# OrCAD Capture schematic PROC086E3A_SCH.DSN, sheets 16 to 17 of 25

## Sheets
16 18. FPD LINK-III SERIALIZER: size C; title: FPD LINK-III SERIALIZER
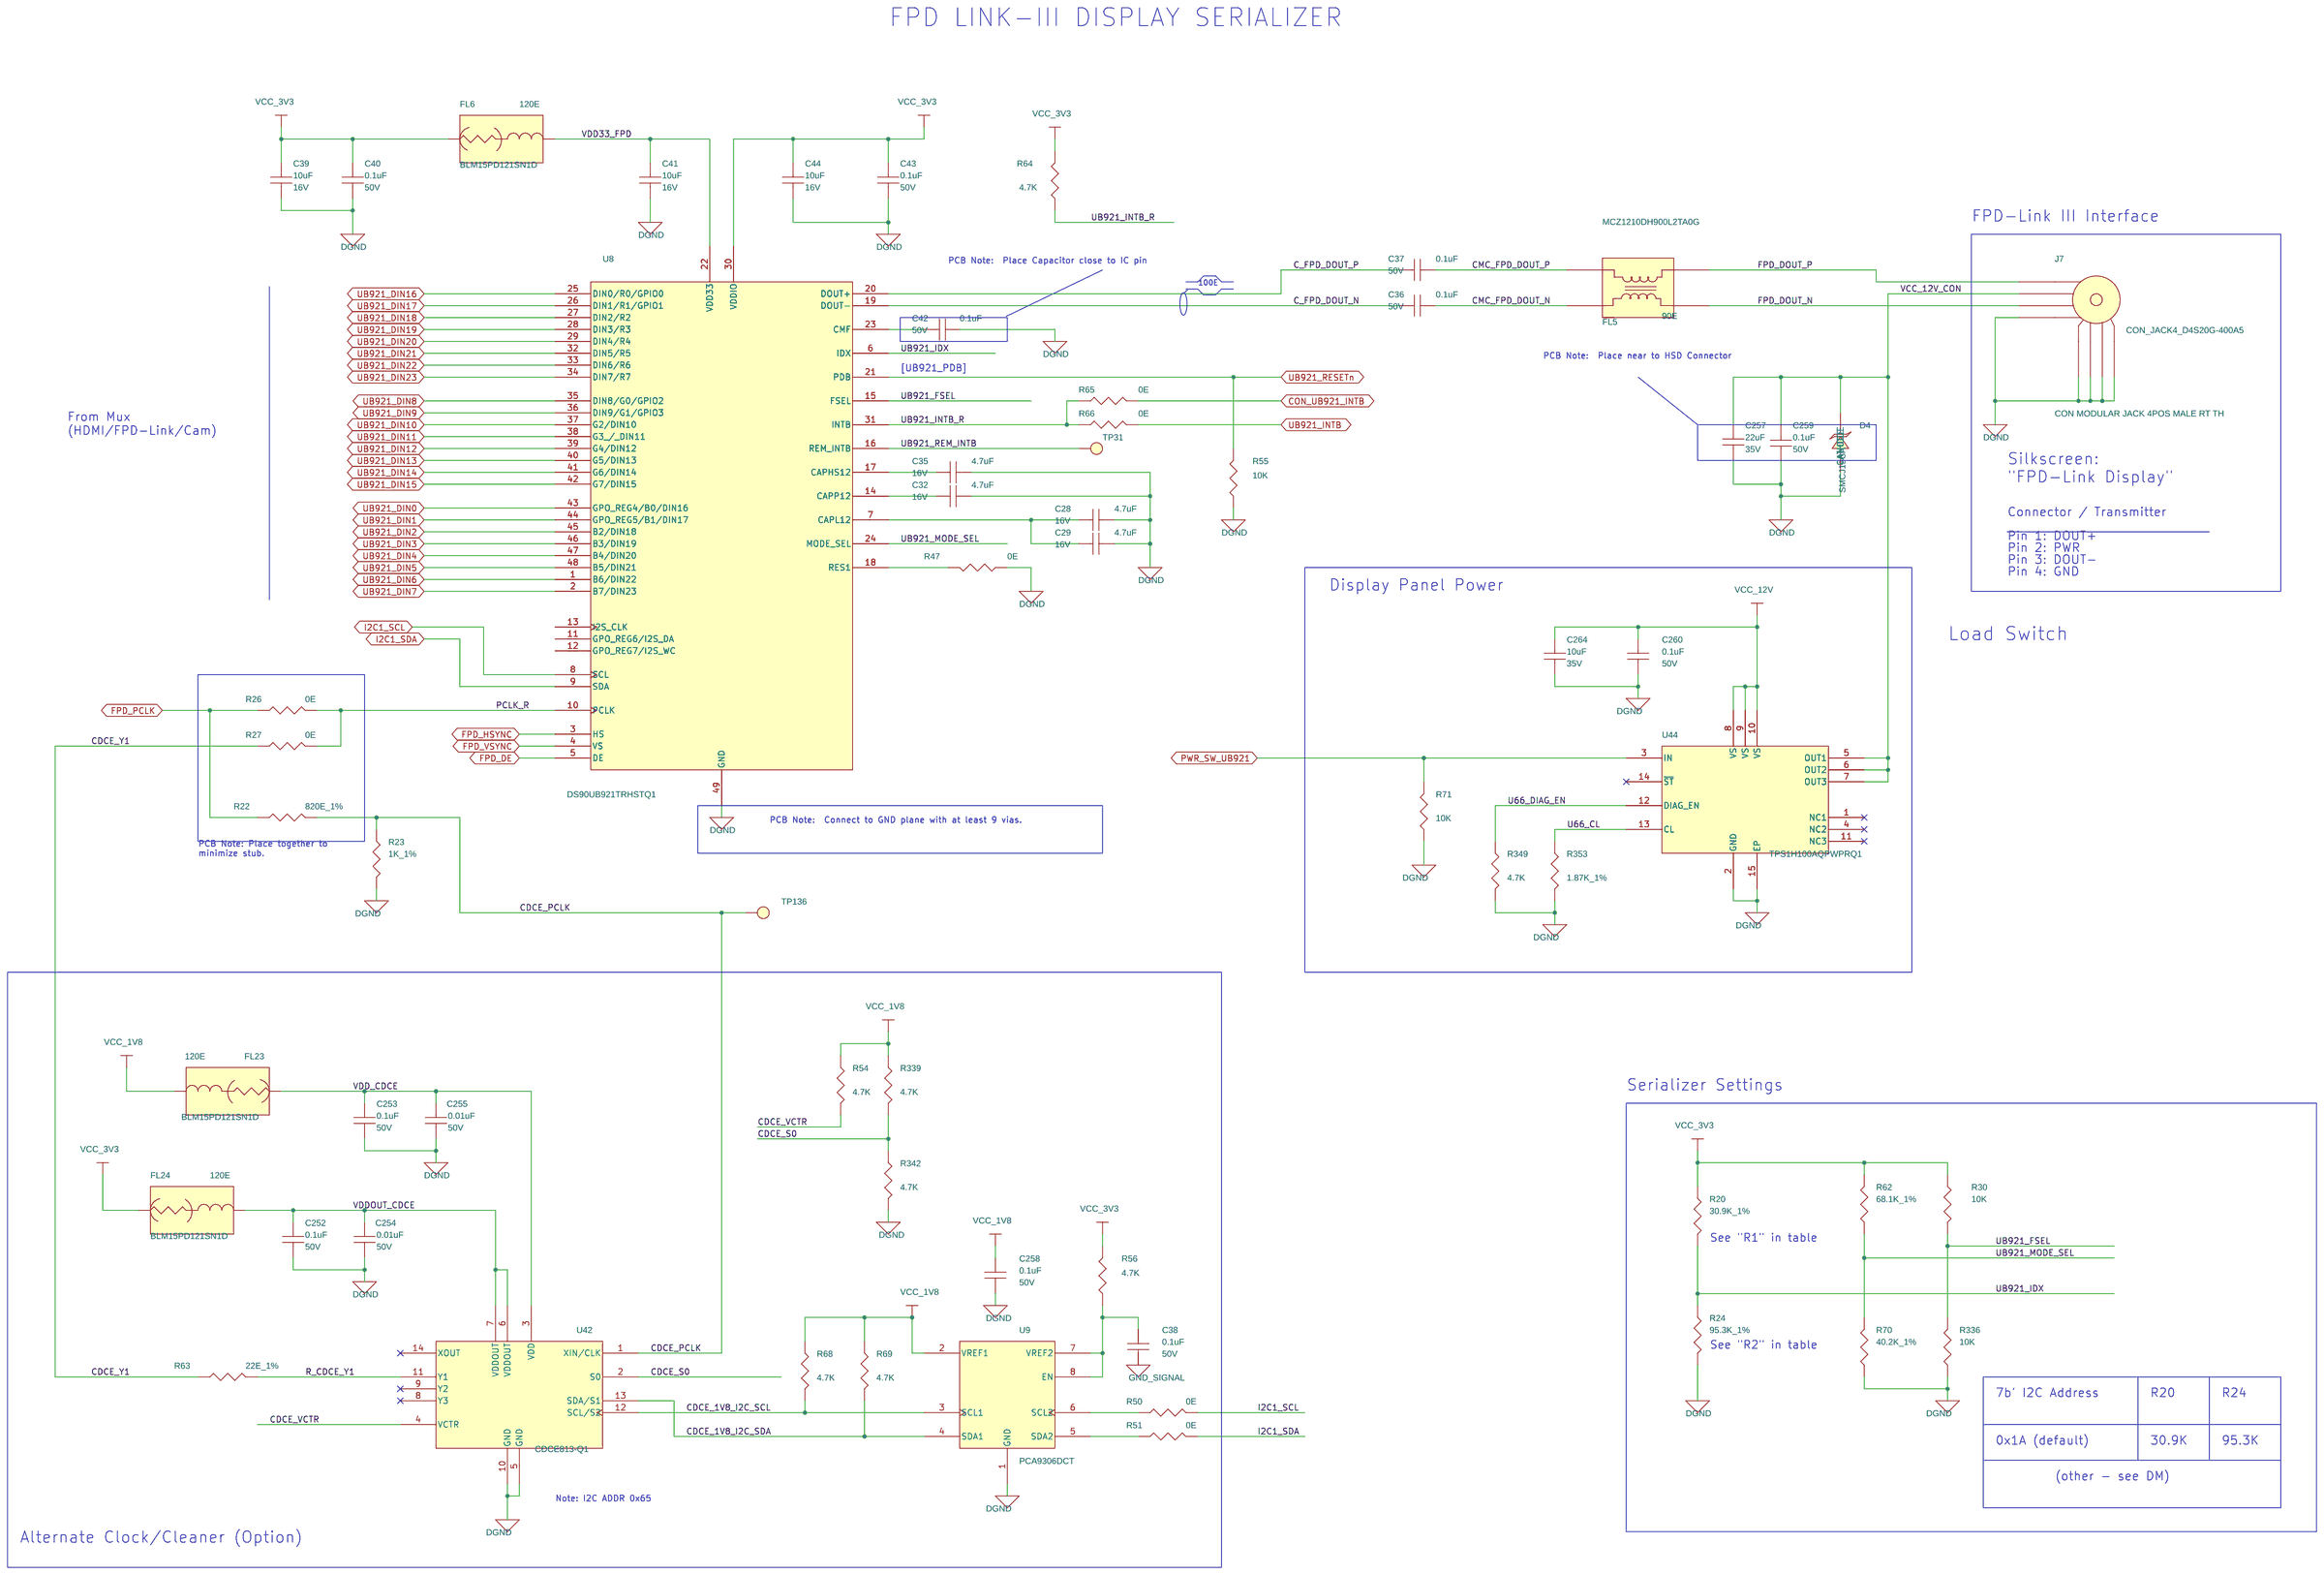
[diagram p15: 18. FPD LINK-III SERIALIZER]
17 20. LI & OV CAMERA INTERFACE: size C; title: OV CAMERA INTERFACE
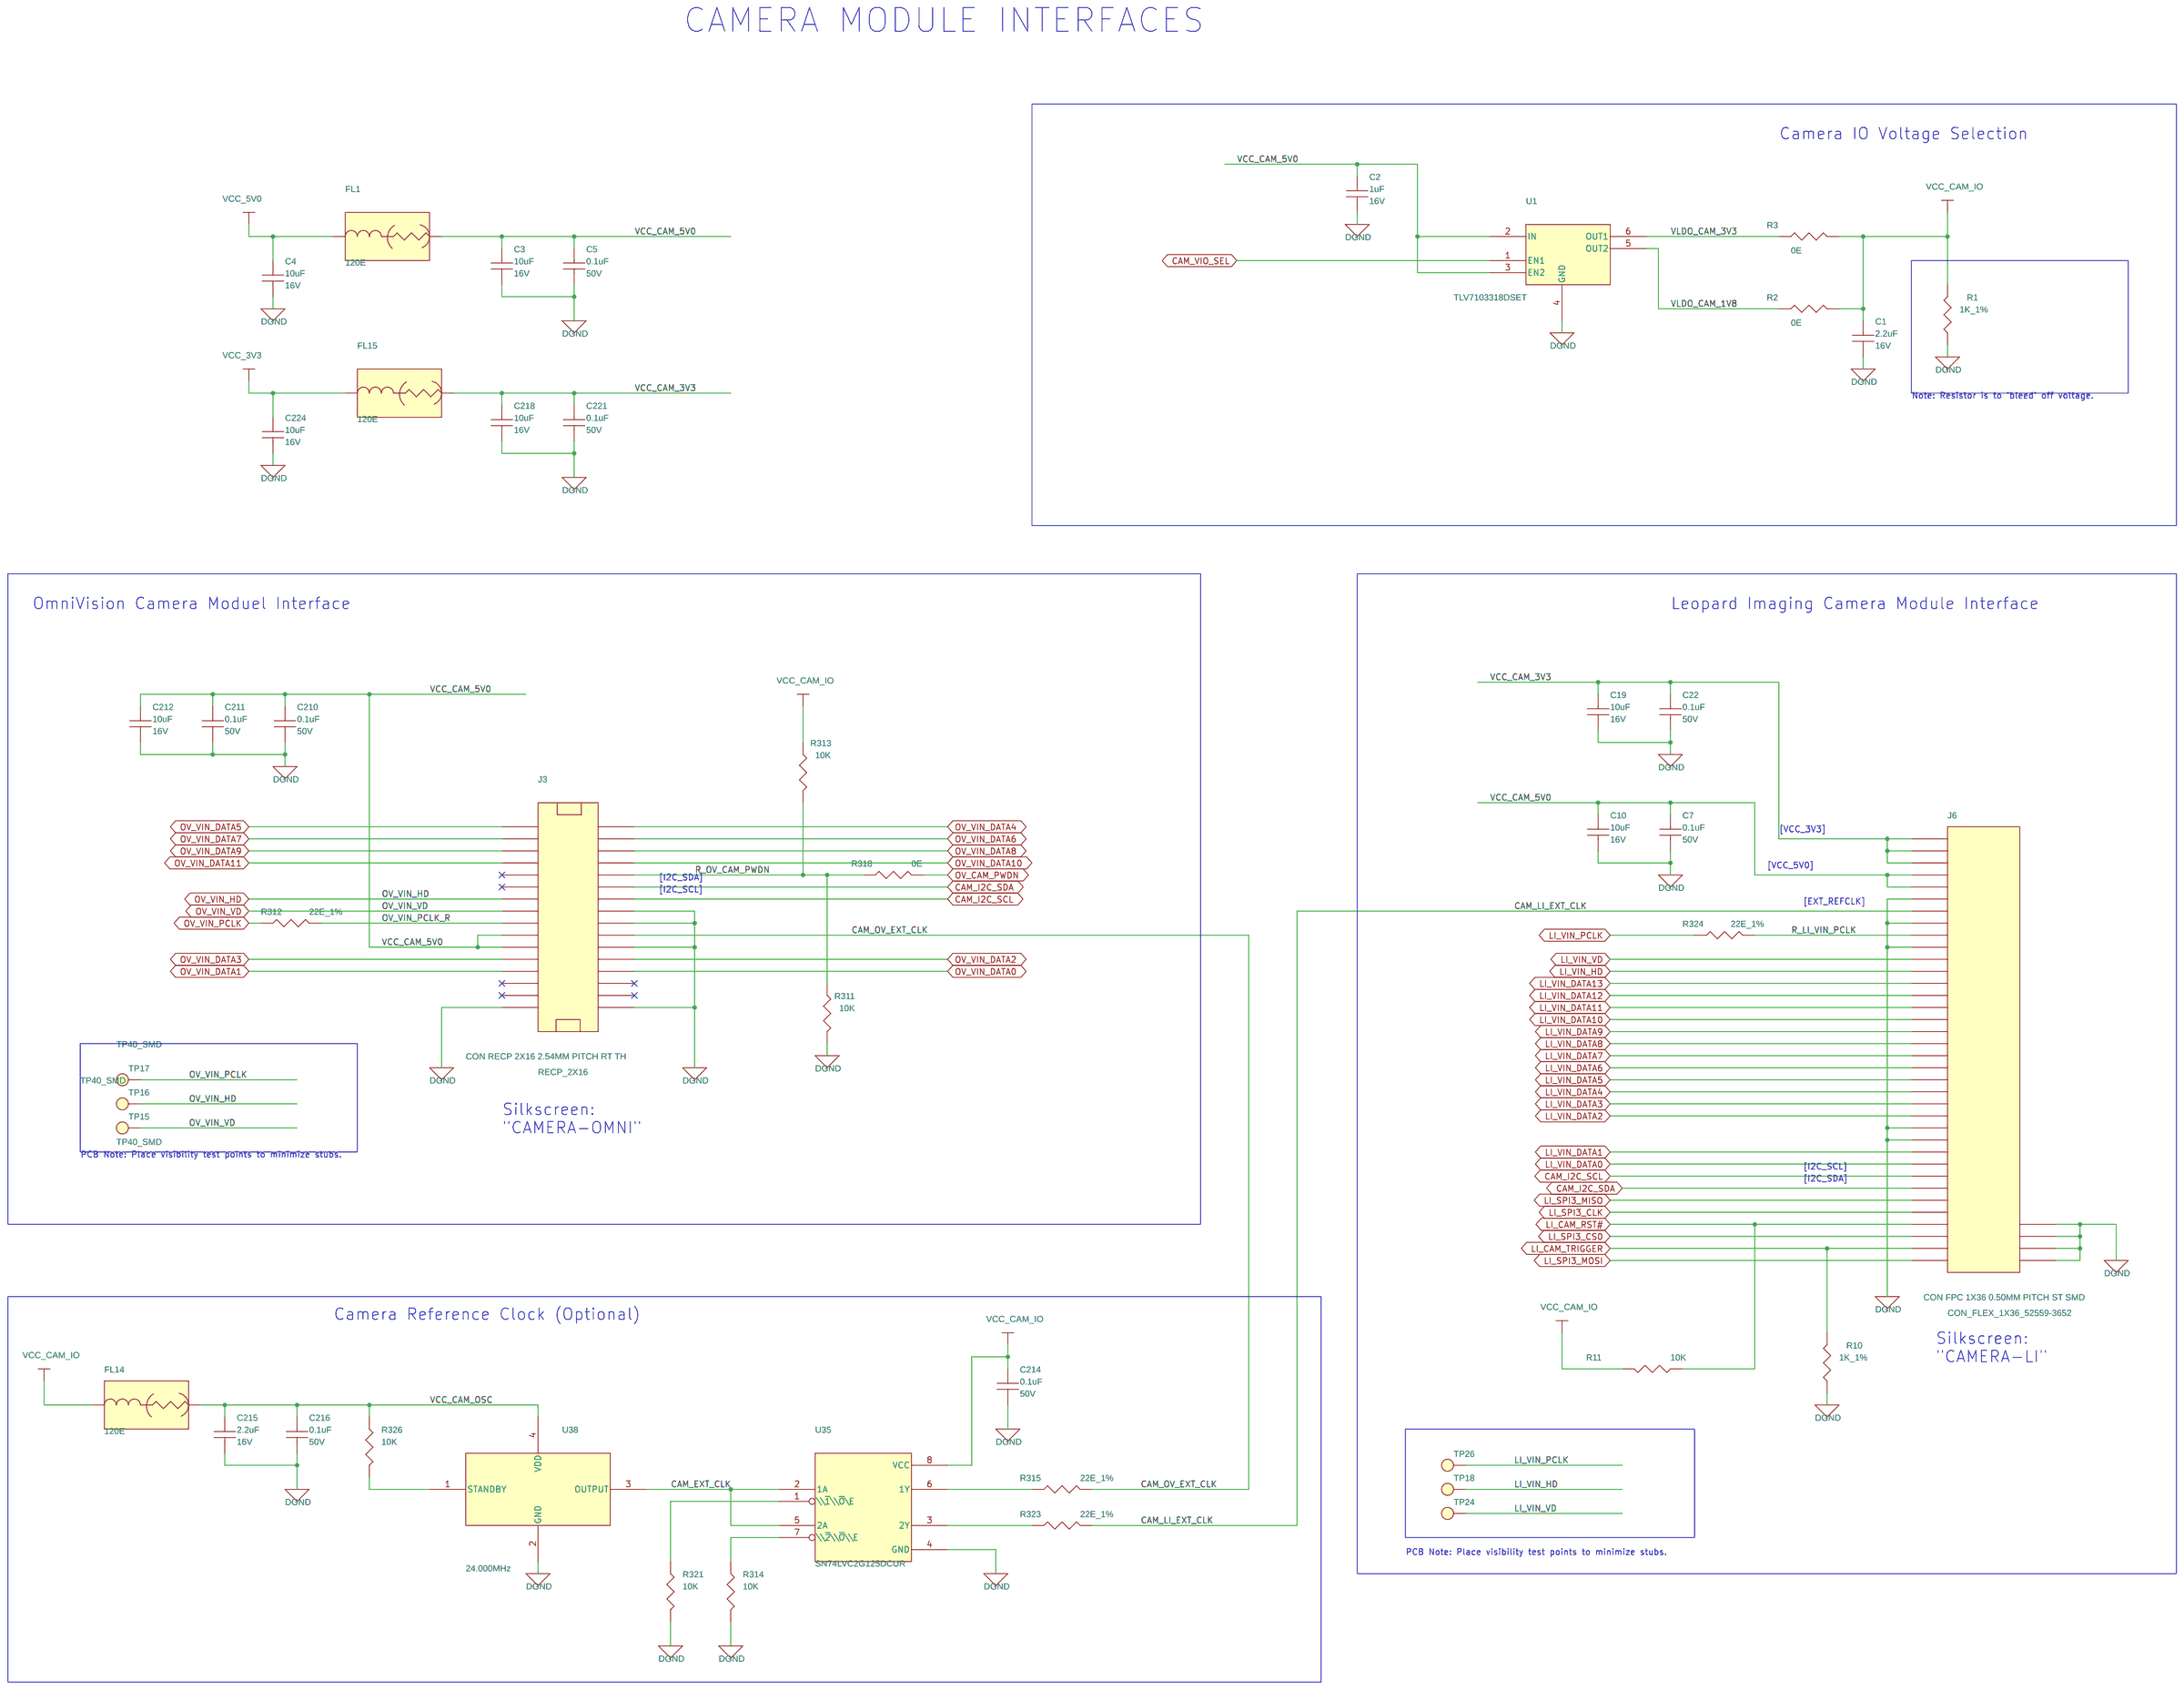
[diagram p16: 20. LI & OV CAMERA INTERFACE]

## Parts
sheet 18. FPD LINK-III SERIALIZER
C28  4.7uF  [CAP0603_1]
C29  4.7uF  [CAP0603_1]
C32  4.7uF  [CAP0603_1]
C35  4.7uF  [CAP0603_1]
C36  0.1uF  [CAP0402_0-75]
C37  0.1uF  [CAP0402_0-75]
C38  0.1uF  [CAP0402_0-75]
C39  10uF  [CAP0603_1]
C40  0.1uF  [CAP0402_0-75]
C41  10uF  [CAP0603_1]
C42  0.1uF  [CAP0402_0-75]
C43  0.1uF  [CAP0402_0-75]
C44  10uF  [CAP0603_1]
C252  0.1uF  [CAP0402_0-75]
C253  0.1uF  [CAP0402_0-75]
C254  0.01uF  [CAP0402_0-75]
C255  0.01uF  [CAP0402_0-75]
C257  22uF  [CAP1206_2]
C258  0.1uF  [CAP0402_0-75]
C259  0.1uF  [CAP0402_0-75]
C260  0.1uF  [CAP0402_0-75]
C264  10uF  [CAP1206_2]
D4  SMCJ15CA  [DIO_SMC]
FL5  90E  [FILT4_MCZ1210DH_60X50_SMD_0-6]
FL6  120E  [EMIFIL_BLM15A_0402_0-6]
FL23  120E  [EMIFIL_BLM15A_0402_0-6]
FL24  120E  [EMIFIL_BLM15A_0402_0-6]
J7  CON_JACK4_D4S20G-400A5  [CON_JACK4_D4S20G-400A5_P_R_T_10-6]
R20  30.9K_1%  [RES0402_0-5]
R22  820E_1%  [RES0402_0-5]
R23  1K_1%  [RES0402_0-5]
R24  95.3K_1%  [RES0402_0-5]
R26  0E  [RES0402_0-5]
R27  0E  [RES0402_0-5]
R30  10K  [RES0402_0-5]
R47  0E  [RES0402_0-5]
R50  0E  [RES0402_0-5]
R51  0E  [RES0402_0-5]
R54  4.7K  [RES0402_0-5]
R55  10K  [RES0402_0-5]
R56  4.7K  [RES0402_0-5]
R62  68.1K_1%  [RES0402_0-5]
R63  22E_1%  [RES0402_0-5]
R64  4.7K  [RES0402_0-5]
R65  0E  [RES0402_0-5]
R66  0E  [RES0402_0-5]
R68  4.7K  [RES0402_0-5]
R69  4.7K  [RES0402_0-5]
R70  40.2K_1%  [RES0402_0-5]
R71  10K  [RES0402_0-5]
R336  10K  [RES0402_0-5]
R339  4.7K  [RES0402_0-5]
R342  4.7K  [RES0402_0-5]
R349  4.7K  [RES0402_0-5]
R353  1.87K_1%  [RES0402_0-5]
TP31  TP40_SMD  [TP40_SMD]
TP136  TP20_SMD  [TP20_SMD]
U8  DS90UB921TRHSTQ1  [QFN48_19-68_280X280_0-8_EP5-2]
U9  PCA9306DCT  [SSOP8_25-59_120X110]
U42  CDCE813-Q1  [TSSOP14_25-59_205X180_1-2]
U44  TPS1H100AQPWPRQ1  [HTSSOP14_TPS1H100-Q1_180X200_1-2]
sheet 20. LI & OV CAMERA INTERFACE
C1  2.2uF  [CAP0805_1-5]
C2  1uF  [CAP0402_0-5]
C3  10uF  [CAP0603_1]
C4  10uF  [CAP0603_1]
C5  0.1uF  [CAP0402_0-75]
C7  0.1uF  [CAP0402_0-75]
C10  10uF  [CAP0603_1]
C19  10uF  [CAP0603_1]
C22  0.1uF  [CAP0402_0-75]
C210  0.1uF  [CAP0402_0-75]
C211  0.1uF  [CAP0402_0-75]
C212  10uF  [CAP0603_1]
C214  0.1uF  [CAP0402_0-75]
C215  2.2uF  [CAP0805_1-5]
C216  0.1uF  [CAP0402_0-75]
C218  10uF  [CAP0603_1]
C221  0.1uF  [CAP0402_0-75]
C224  10uF  [CAP0603_1]
FL1  120E  [EMIFIL_BLM15A_0402_0-6]
FL14  120E  [EMIFIL_BLM15A_0402_0-6]
FL15  120E  [EMIFIL_BLM15A_0402_0-6]
J3  RECP_2X16  [RECPT_2X16_SSW-116-D-RA_R_T_5]
J6  CON_FLEX_1X36_52559-3652  [CON_FLEX1X36_52559-36_S_S_S_5-3]
R1  1K_1%  [RES0402_0-5]
R2  0E  [RES0402_0-5]
R3  0E  [RES0402_0-5]
R10  1K_1%  [RES0402_0-5]
R11  10K  [RES0402_0-5]
R311  10K  [RES0402_0-5]
R312  22E_1%  [RES0402_0-5]
R313  10K  [RES0402_0-5]
R314  10K  [RES0402_0-5]
R315  22E_1%  [RES0402_0-5]
R318  0E  [RES0402_0-5]
R321  10K  [RES0402_0-5]
R323  22E_1%  [RES0402_0-5]
R324  22E_1%  [RES0402_0-5]
R326  10K  [RES0402_0-5]
TP15  TP40_SMD  [TP40_SMD]
TP16  TP40_SMD  [TP40_SMD]
TP17  TP40_SMD  [TP40_SMD]
TP18  TP40_SMD  [TP40_SMD]
TP24  TP40_SMD  [TP40_SMD]
TP26  TP40_SMD  [TP40_SMD]
U1  TLV7103318DSET  [WSON6_19-68_60X60]
U35  SN74LVC2G125DCUR  [VSSOP8_19-68_85X95]
U38  24.000MHz  [OSC4_ASDMB_100X85_SMD_0-9]

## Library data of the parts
C28 C29 C32 C35 = CAP: CAP CERAMIC 4.7uF 16V 10% X6S 0603; Chkd/date: MANIRAJA/050618; Crtd /date: ALVY/050618; Custom_Duty: 15%; Customs_HS_Code: 85322990; Distributor_name: DIGIKEY; Distributor_part_number: 445-9118-1-ND; Footprint Path: Y:\MIS_DATABASE\Library\ALTIUM_TOOL\PCB_FOOTPRINTS\Altium_Footprint_Lib.PcbLib; Height: 1.00MM; Library Path: Y:\MIS_DATABASE\Library\ALTIUM_TOOL\SCHEMATICS_PARTS\MS_DISCRETE_Library.schlib; Mfr_name: TDK CORPORATION; Mfr_part_number: C1608X6S1C475K080AC; Mistral Part No: 120018060012-R; Package: 0603; Part_type: CAPACITORS\CERAMIC; Project: NPOL_RDAQ_ONBOARD-RX; RoHS: RoHS; Temperature: -55°C+105°C; Tolerance: 10%; Voltage: 16V; Wattage: NA; Weight: 2mg; Datasheet: Y:\MIS_DATABASE\DATASHEETS\CAPACITORS\TDK_C-SER-JUL17.PDF
C5 C7 C22 C36-C38 C40 C42 C43 C210 C211 C214 C216 C221 C252 C253 C258-C260 = CAP: CAP CERAMIC 0.1uF 50V 10% X7R 0402; Chkd/date: VASANTHA/281216; Crtd /date: CHAITHANYA/051011; Custom_Duty: 15%; Customs_HS_Code: 85322990; Distributor_name: DIGIKEY; Distributor_part_number: 445-173610-1-ND; Footprint Path: Y:\MIS_DATABASE\Library\ALTIUM_TOOL\PCB_FOOTPRINTS\Altium_Footprint_Lib.PcbLib; Height: 0.60MM; Library Path: Y:\MIS_DATABASE\Library\ALTIUM_TOOL\SCHEMATICS_PARTS\MS_DISCRETE_Library.schlib; Mfr_name: TDK CORPORATION; Mfr_part_number: C1005X7R1H104K050BE; Mistral Part No: 120011100014-R; Package: 0402; Part_type: CAPACITORS\CERAMIC; Project: VP-4000-BASE-BOARD; RoHS: RoHS; Temperature: -55°C+125°C; Tolerance: 10%; Voltage: 50V; Wattage: NA; Weight: 0.65mg; Datasheet: Y:\MIS_DATABASE\DATASHEETS\CAPACITORS\TDK_C-SER_FEB19.PDF
C3 C4 C10 C19 C39 C41 C44 C212 C218 C224 = CAP: CAP CERAMIC 10uF 16V 20% X6S 0603; Chkd/date: VASANTHA/170117; Crtd /date: VASANTHA/170117; Custom_Duty: 15%; Customs_HS_Code: 85322990; Distributor_name: DIGIKEY; Distributor_part_number: 490-7198-1-ND; Footprint Path: Y:\MIS_DATABASE\Library\ALTIUM_TOOL\PCB_FOOTPRINTS\Altium_Footprint_Lib.PcbLib; Height: 0.90MM; Library Path: Y:\MIS_DATABASE\Library\ALTIUM_TOOL\SCHEMATICS_PARTS\MS_DISCRETE_Library.schlib; Mfr_name: MURATA; Mfr_part_number: GRM188C81C106MA73D; Mistral Part No: 120017010004-R; Package: 0603; Part_type: CAPACITORS\CERAMIC; Project: TRMM_SMART-M_PS; RoHS: RoHS; Temperature: -55°C+105°C; Tolerance: 20%; Voltage: 16V; Wattage: NA; Weight: 6.3mg; Datasheet: Y:\MIS_DATABASE\DATASHEETS\CAPACITORS\MURATA-GXX-SER_NOV17.PDF
C254 C255 = CAP: CAP CERAMIC 0.01uF 50V 10% X7R 0402; Chkd/date: SHREESHAIL/301105; Crtd /date: MAZHAR/040505; Custom_Duty: 15%; Customs_HS_Code: 85322990; Distributor_name: DIGIKEY; Distributor_part_number: 399-3066-1-ND; Footprint Path: Y:\MIS_DATABASE\Library\ALTIUM_TOOL\PCB_FOOTPRINTS\Altium_Footprint_Lib.PcbLib; Height: 0.55MM; Library Path: Y:\MIS_DATABASE\Library\ALTIUM_TOOL\SCHEMATICS_PARTS\MS_DISCRETE_Library.schlib; Mfr_name: KEMET; Mfr_part_number: C0402C103K5RACTU; Mistral Part No: 120009030025-R; Package: 0402; Part_type: CAPACITORS\CERAMIC; Project: G4_SVGA; RoHS: RoHS; Temperature: -55°C+125°C; Tolerance: 10%; Voltage: 50V; Wattage: NA; Weight: 0.65mg; Datasheet: Y:\MIS_DATABASE\DATASHEETS\CAPACITORS\KEMET-C-X7R.PDF
C257 = CAP: CAP CERAMIC 22uF 35V 20% X5R 1206; Chkd/date: MANIRAJA/130318; Crtd /date: MANIRAJA/130318; Custom_Duty: 15%; Customs_HS_Code: 85322990; Distributor_name: DIGIKEY; Distributor_part_number: 445-8045-1-ND; Footprint Path: Y:\MIS_DATABASE\Library\ALTIUM_TOOL\PCB_FOOTPRINTS\Altium_Footprint_Lib.PcbLib; Height: 1.80MM; Library Path: Y:\MIS_DATABASE\Library\ALTIUM_TOOL\SCHEMATICS_PARTS\MS_DISCRETE_Library.schlib; Mfr_name: TDK CORPORATION; Mfr_part_number: C3216X5R1V226M160AC; Mistral Part No: 120018030003-R; Package: 1206; Part_type: CAPACITORS\CERAMIC; Project: TI_SVB_MAXWELL_VPS; RoHS: RoHS; Temperature: -55°C+85°C; Tolerance: 20%; Voltage: 35V; Wattage: NA; Weight: 16.2mg; Datasheet: Y:\MIS_DATABASE\DATASHEETS\CAPACITORS\C3216X5R1V226M160AC.PDF
C264 = CAP: CAP CERAMIC 10uF 35V 10% X5R 1206; Chkd/date: MANIRAJA/160519; Crtd /date: ALVY/160519; Custom_Duty: 15%; Customs_HS_Code: 85322990; Distributor_name: DIGIKEY; Distributor_part_number: 587-2484-1-ND; Footprint Path: Y:\MIS_DATABASE\Library\ALTIUM_TOOL\PCB_FOOTPRINTS\Altium_Footprint_Lib.PcbLib; Height: 1.80MM; Library Path: Y:\MIS_DATABASE\Library\ALTIUM_TOOL\SCHEMATICS_PARTS\MS_DISCRETE_Library.schlib; Mfr_name: TAIYO YUDEN; Mfr_part_number: GMK316BJ106KL-T; Mistral Part No: 120019050012-R; Package: 1206; Part_type: CAPACITORS\CERAMIC; Project: J7ES_SOM_DUAL-LEO_PMIC; RoHS: RoHS; Temperature: -55°C+85°C; Tolerance: 10%; Voltage: 35V; Wattage: NA; Weight: 16.2mg; Datasheet: Y:\MIS_DATABASE\DATASHEETS\CAPACITORS\TY-EMKXXX-2019.PDF
D4 = DIODE_TVS: DIODE TVS 1500W 15V SMC; Chkd/date: SUHAS/061010; Crtd /date: MAZHAR/011007; Custom_Duty: 15%; Customs_HS_Code: 85412900; Distributor_name: DIGIKEY; Distributor_part_number: SMCJ15CALFCT-ND; Height: 2.62MM; Mfr_name: LITTLE FUSE; Mistral Part No: 130009030286-R; Package: SMC; Part_type: DIODE\TVS; Project: TELEMETRY ENCODER; RoHS: RoHS; Temperature: -55°C+150°C; Voltage: 15V; Wattage: 1500W; Weight: 0.21g; Datasheet: Y:\MIS_DATABASE\DATASHEETS\DISCRETES\DIODES\SMCJ-LITT.PDF
FL5 = EMIFILTER_ACM: FILTER COMMON MODE 90E 100mA SMD; Chkd/date: MANIRAJA/220818; Crtd /date: ALVY/220818; Custom_Duty: 24%; Customs_HS_Code: 85437099; Distributor_name: DIGIKEY; Distributor_part_number: 445-174550-1-ND; Footprint Path: Y:\MIS_DATABASE\Library\ALTIUM_TOOL\PCB_FOOTPRINTS\Altium_Footprint_Lib.PcbLib; Height: 0.60MM; Library Path: Y:\MIS_DATABASE\Library\ALTIUM_TOOL\SCHEMATICS_PARTS\MS_FILTER_Library.schlib; Mfr_name: TDK CORPORATION; Mfr_part_number: MCZ1210DH900L2TA0G; Mistral Part No: 130018080027-R; Package: SMD; Part_type: FILTER; Project: TI_J7ES_EVM_FUSION2_SER_CAP; RoHS: RoHS; Temperature: -40°C+85°C; Tolerance: 25%; Voltage: NA; Wattage: NA; Weight: 3mg; Datasheet: Y:\MIS_DATABASE\DATASHEETS\ICS\MISC\MCZ1210DH-SER.PDF
FL1 FL6 FL14 FL15 FL23 FL24 = EMIFILTER_IND: IND FERRITE BEAD CHIP 120E 1.3A 0402; Chkd/date: VASANTHA/010117; Crtd /date: CHAITHANYA/150312; Custom_Duty: 24%; Customs_HS_Code: 85437099; Distributor_name: DIGIKEY; Distributor_part_number: 490-5203-1-ND; Footprint Path: Y:\MIS_DATABASE\Library\ALTIUM_TOOL\PCB_FOOTPRINTS\Altium_Footprint_Lib.PcbLib; Height: 0.55MM; Library Path: Y:\MIS_DATABASE\Library\ALTIUM_TOOL\SCHEMATICS_PARTS\MS_FILTER_Library.schlib; Mfr_name: MURATA; Mfr_part_number: BLM15PD121SN1D; Mistral Part No: 130012030043-R; Package: 0402; Part_type: FILTER; Project: GEN_3-8; RoHS: RoHS; Temperature: -55°C+125°C; Tolerance: 25%; Voltage: NA; Wattage: NA; Weight: 0.65mg; Datasheet: Y:\MIS_DATABASE\DATASHEETS\DISCRETES\INDUCTORS\BLM15X-SER.PDF
J7 = CON_JACK4_EXG.0B.304: CON MODULAR JACK 4POS MALE RT TH; Chkd/date: MANIRAJA/031018; Crtd /date: ALVY/070818; Custom_Duty: 24%; Customs_HS_Code: 85369090; Distributor_name: DIGIKEY; Distributor_part_number: 1868-1516-1-ND; Footprint Path: Y:\MIS_DATABASE\Library\ALTIUM_TOOL\PCB_FOOTPRINTS\Altium_Footprint_Lib.PcbLib; Height: 10.60MM; Library Path: Y:\MIS_DATABASE\Library\ALTIUM_TOOL\SCHEMATICS_PARTS\MS_CONNECTOR_Library.schlib; Mfr_name: ROSENBERGER; Mfr_part_number: D4S20G-400A5-C; Mistral Part No: 150018080004-R; Package: THRU-HOLE; Part_type: CONNECTOR\JACK; Project: TI_J7ES_EVM_IB; RoHS: RoHS; Temperature: -40°C+105°C; Tolerance: NA; Voltage: NA; Wattage: NA; Weight: 8.6g; Datasheet: Y:\MIS_DATABASE\DATASHEETS\CONNECTORS\D4S20G-400A5-Y.PDF
R20 = RESISTOR: RES 30.9K 1/10W 1% 0402; Chkd/date: MAZHAR/080311; Crtd /date: BAVISH/230211; Custom_Duty: 15%; Customs_HS_Code: 85332119; Distributor_name: DIGIKEY; Distributor_part_number: P30.9KLCT-ND; Footprint Path: Y:\MIS_DATABASE\Library\ALTIUM_TOOL\PCB_FOOTPRINTS\Altium_Footprint_Lib.PcbLib; Height: 0.40MM; Library Path: Y:\MIS_DATABASE\Library\ALTIUM_TOOL\SCHEMATICS_PARTS\MS_DISCRETE_Library.schlib; Mfr_name: PANASONIC-ECG; Mfr_part_number: ERJ-2RKF3092X; Mistral Part No: 110011020022-R; Package: 0402; Part_type: RESISTORS\FIXED; Project: GOLDEN-I; RoHS: RoHS; Temperature: -55°C+155°C; Tolerance: 1%; Voltage: NA; Wattage: 1/10W; Weight: 0.8mg; Datasheet: Y:\MIS_DATABASE\DATASHEETS\RESISTORS\PAN-ERJSER_NOV17.PDF
R22 = RESISTOR: RES 820E 1/10W 1% 0402; Assembly_Instruction: DNI; Chkd/date: MAZHAR/150709; Crtd /date: USMAN/020409; Custom_Duty: 15%; Customs_HS_Code: 85332119; Distributor_name: DIGIKEY; Distributor_part_number: P820LCT-ND; Footprint Path: Y:\MIS_DATABASE\Library\ALTIUM_TOOL\PCB_FOOTPRINTS\Altium_Footprint_Lib.PcbLib; Height: 0.40MM; Library Path: Y:\MIS_DATABASE\Library\ALTIUM_TOOL\SCHEMATICS_PARTS\MS_DISCRETE_Library.schlib; Mfr_name: PANASONIC-ECG; Mfr_part_number: ERJ-2RKF8200X; Mistral Part No: 110009031230-R; Package: 0402; Part_type: RESISTORS\FIXED; Project: AXON; RoHS: RoHS; Temperature: -55°C+155°C; Tolerance: 1%; Voltage: NA; Wattage: 1/10W; Weight: 0.8mg; Datasheet: Y:\MIS_DATABASE\DATASHEETS\RESISTORS\PAN-ERJSER_NOV17.PDF
R1 R10 R23 = RESISTOR: RES 1K 1/10W 1% 0402; Chkd/date: VASANTHA/281216; Crtd /date: MAZHAR/150506; Custom_Duty: 15%; Customs_HS_Code: 85332119; Distributor_name: DIGIKEY; Distributor_part_number: P1.00KLCT-ND; Footprint Path: Y:\MIS_DATABASE\Library\ALTIUM_TOOL\PCB_FOOTPRINTS\Altium_Footprint_Lib.PcbLib; Height: 0.40MM; Library Path: Y:\MIS_DATABASE\Library\ALTIUM_TOOL\SCHEMATICS_PARTS\MS_DISCRETE_Library.schlib; Mfr_name: PANASONIC-ECG; Mfr_part_number: ERJ-2RKF1001X; Mistral Part No: 110009030411-R; Package: 0402; Part_type: RESISTORS\FIXED; Project: VOCERA; RoHS: RoHS; Temperature: -55°C+155°C; Tolerance: 1%; Voltage: NA; Wattage: 1/10W; Weight: 0.8mg; Datasheet: Y:\MIS_DATABASE\DATASHEETS\RESISTORS\PAN-ERJSER_NOV17.PDF
R24 = RESISTOR: RES 95.3K 1/16W 1% 0402; Chkd/date: VASANTHA/061216; Crtd /date: CHAITHANYA/060612; Custom_Duty: 15%; Customs_HS_Code: 85332119; Distributor_name: DIGIKEY; Distributor_part_number: 541-95.3KLCT-ND; Footprint Path: Y:\MIS_DATABASE\Library\ALTIUM_TOOL\PCB_FOOTPRINTS\Altium_Footprint_Lib.PcbLib; Height: 0.40MM; Library Path: Y:\MIS_DATABASE\Library\ALTIUM_TOOL\SCHEMATICS_PARTS\MS_DISCRETE_Library.schlib; Mfr_name: VISHAY; Mfr_part_number: CRCW040295K3FKED; Mistral Part No: 110012060003-R; Package: 0402; Part_type: RESISTORS\FIXED; Project: GEN_3-8_DB; RoHS: RoHS; Temperature: -55°C+155°C; Tolerance: 1%; Voltage: NA; Wattage: 1/16W; Weight: 0.65mg; Datasheet: Y:\MIS_DATABASE\DATASHEETS\RESISTORS\CRCW0603.PDF
R2 R3 R26 R47 R65 R318 = RESISTOR: RES 0E 1/10W JUMPER 0402; Chkd/date: VASANTHA/061216; Crtd /date: NAVEED/201014; Custom_Duty: 15%; Customs_HS_Code: 85332119; Distributor_name: DIGIKEY; Distributor_part_number: P0.0JCT-ND; Footprint Path: Y:\MIS_DATABASE\Library\ALTIUM_TOOL\PCB_FOOTPRINTS\Altium_Footprint_Lib.PcbLib; Height: 0.40MM; IBISSP_MODLES: VALUE REPEATING 2 TIME; Library Path: Y:\MIS_DATABASE\Library\ALTIUM_TOOL\SCHEMATICS_PARTS\MS_DISCRETE_Library.schlib; Mfr_name: PANASONIC-ECG; Mfr_part_number: ERJ-2GE0R00X; Mistral Part No: 110018030052-R; Package: 0402; Part_type: RESISTORS\FIXED; Project: AEGIS POM; RoHS: RoHS; Temperature: -55°C+155°C; Tolerance: NA; Voltage: NA; Wattage: 1/10W; Weight: 0.8mg; Datasheet: Y:\MIS_DATABASE\DATASHEETS\RESISTORS\PAN-ERJSER_NOV17.PDF
R27 R50 R51 = RESISTOR: RES 0E 1/10W JUMPER 0402; Assembly_Instruction: DNI; Chkd/date: VASANTHA/061216; Crtd /date: NAVEED/201014; Custom_Duty: 15%; Customs_HS_Code: 85332119; Distributor_name: DIGIKEY; Distributor_part_number: P0.0JCT-ND; Footprint Path: Y:\MIS_DATABASE\Library\ALTIUM_TOOL\PCB_FOOTPRINTS\Altium_Footprint_Lib.PcbLib; Height: 0.40MM; IBISSP_MODLES: VALUE REPEATING 2 TIME; Library Path: Y:\MIS_DATABASE\Library\ALTIUM_TOOL\SCHEMATICS_PARTS\MS_DISCRETE_Library.schlib; Mfr_name: PANASONIC-ECG; Mfr_part_number: ERJ-2GE0R00X; Mistral Part No: 110018030052-R; Package: 0402; Part_type: RESISTORS\FIXED; Project: AEGIS POM; RoHS: RoHS; Temperature: -55°C+155°C; Tolerance: NA; Voltage: NA; Wattage: 1/10W; Weight: 0.8mg; Datasheet: Y:\MIS_DATABASE\DATASHEETS\RESISTORS\PAN-ERJSER_NOV17.PDF
R30 R311 R313 = RESISTOR: RES 10K 1/16W 5% 0402; Assembly_Instruction: DNI; Chkd/date: VASANTHA/061216; Crtd /date: MAZHAR/230805; Custom_Duty: 15%; Customs_HS_Code: 85332119; Distributor_name: DIGIKEY; Distributor_part_number: 311-10KJRCT-ND; Footprint Path: Y:\MIS_DATABASE\Library\ALTIUM_TOOL\PCB_FOOTPRINTS\Altium_Footprint_Lib.PcbLib; Height: 0.40MM; Library Path: Y:\MIS_DATABASE\Library\ALTIUM_TOOL\SCHEMATICS_PARTS\MS_DISCRETE_Library.schlib; Mfr_name: YAGEO AMERICA; Mfr_part_number: RC0402JR-0710KL; Mistral Part No: 110011060021-R; Package: 0402; Part_type: RESISTORS\FIXED; Project: HSE; RoHS: RoHS; Temperature: -55°C+155°C; Tolerance: 5%; Voltage: NA; Wattage: 1/16W; Weight: 0.65mg; Datasheet: Y:\MIS_DATABASE\DATASHEETS\RESISTORS\RCXXXXL-SER_MAR18.PDF
R54 R56 R64 R68 R69 R339 R349 = RESISTOR: RES 4.7K 1/16W 5% 0402; Chkd/date: VASANTHA/281216; Crtd /date: BAVISH/010611; Custom_Duty: 15%; Customs_HS_Code: 85332119; Distributor_name: DIGIKEY; Distributor_part_number: 541-4.7KJCT-ND; Footprint Path: Y:\MIS_DATABASE\Library\ALTIUM_TOOL\PCB_FOOTPRINTS\Altium_Footprint_Lib.PcbLib; Height: 0.40MM; Library Path: Y:\MIS_DATABASE\Library\ALTIUM_TOOL\SCHEMATICS_PARTS\MS_DISCRETE_Library.schlib; Mfr_name: VISHAY; Mfr_part_number: CRCW04024K70JNED; Mistral Part No: 110011060001-R; Package: 0402; Part_type: RESISTORS\FIXED; Project: AM4515_EVM_LCD; RoHS: RoHS; Temperature: -55°C+155°C; Tolerance: 5%; Voltage: NA; Wattage: 1/16W; Weight: 0.65mg; Datasheet: Y:\MIS_DATABASE\DATASHEETS\RESISTORS\CRCW0603.PDF
R11 R55 R71 R314 R321 R326 R336 = RESISTOR: RES 10K 1/16W 5% 0402; Chkd/date: VASANTHA/061216; Crtd /date: MAZHAR/230805; Custom_Duty: 15%; Customs_HS_Code: 85332119; Distributor_name: DIGIKEY; Distributor_part_number: 311-10KJRCT-ND; Footprint Path: Y:\MIS_DATABASE\Library\ALTIUM_TOOL\PCB_FOOTPRINTS\Altium_Footprint_Lib.PcbLib; Height: 0.40MM; Library Path: Y:\MIS_DATABASE\Library\ALTIUM_TOOL\SCHEMATICS_PARTS\MS_DISCRETE_Library.schlib; Mfr_name: YAGEO AMERICA; Mfr_part_number: RC0402JR-0710KL; Mistral Part No: 110011060021-R; Package: 0402; Part_type: RESISTORS\FIXED; Project: HSE; RoHS: RoHS; Temperature: -55°C+155°C; Tolerance: 5%; Voltage: NA; Wattage: 1/16W; Weight: 0.65mg; Datasheet: Y:\MIS_DATABASE\DATASHEETS\RESISTORS\RCXXXXL-SER_MAR18.PDF
R62 = RESISTOR: RES 68.1K 1/16W 1% 0402; Assembly_Instruction: DNI; Chkd/date: JEBRAN/110815; Crtd /date: JEBRAN/110815; Custom_Duty: 15%; Customs_HS_Code: 85332119; Distributor_name: DIGIKEY; Distributor_part_number: 541-68.1KLCT-ND; Footprint Path: Y:\MIS_DATABASE\Library\ALTIUM_TOOL\PCB_FOOTPRINTS\Altium_Footprint_Lib.PcbLib; Height: 0.40MM; Library Path: Y:\MIS_DATABASE\Library\ALTIUM_TOOL\SCHEMATICS_PARTS\MS_DISCRETE_Library.schlib; Mfr_name: VISHAY; Mfr_part_number: CRCW040268K1FKED; Mistral Part No: 110015080021-R; Package: 0402; Part_type: RESISTORS\FIXED; Project: OCTASIC_3000; RoHS: RoHS; Temperature: -55°C+155°C; Tolerance: 1%; Voltage: NA; Wattage: 1/16W; Weight: 0.65mg; Datasheet: Y:\MIS_DATABASE\DATASHEETS\RESISTORS\CRCW0603.PDF
R63 R312 R315 R323 R324 = RESISTOR: RES 22E 1/16W 1% 0402; Chkd/date: SUHAS/290910; Crtd /date: MAZHAR/090909; Cust_part_number: 4700-80047E; Custom_Duty: 15%; Customs_HS_Code: 85332119; Distributor_name: DIGIKEY; Distributor_part_number: 311-22.0LRCT-ND; Footprint Path: Y:\MIS_DATABASE\Library\ALTIUM_TOOL\PCB_FOOTPRINTS\Altium_Footprint_Lib.PcbLib; Height: 0.40MM; Library Path: Y:\MIS_DATABASE\Library\ALTIUM_TOOL\SCHEMATICS_PARTS\MS_DISCRETE_Library.schlib; Mfr_name: YAGEO AMERICA; Mfr_part_number: RC0402FR-0722RL; Mistral Part No: 110009090004-R; Package: 0402; Part_type: RESISTORS\FIXED; Project: VMEFMCD; RoHS: RoHS; Temperature: -55°C+155°C; Tolerance: 1%; Voltage: NA; Wattage: 1/16W; Weight: 0.65mg; Datasheet: Y:\MIS_DATABASE\DATASHEETS\RESISTORS\RCXXXXL-SER_MAR18.PDF
R66 = RESISTOR: RES 0E 1/10W JUMPER 0402; Assembly_instruction: DNI; Chkd/date: VASANTHA/061216; Crtd /date: NAVEED/201014; Custom_Duty: 15%; Customs_HS_Code: 85332119; Distributor_name: DIGIKEY; Distributor_part_number: P0.0JCT-ND; Footprint Path: Y:\MIS_DATABASE\Library\ALTIUM_TOOL\PCB_FOOTPRINTS\Altium_Footprint_Lib.PcbLib; Height: 0.40MM; IBISSP_MODLES: VALUE REPEATING 2 TIME; Library Path: Y:\MIS_DATABASE\Library\ALTIUM_TOOL\SCHEMATICS_PARTS\MS_DISCRETE_Library.schlib; Mfr_name: PANASONIC-ECG; Mfr_part_number: ERJ-2GE0R00X; Mistral Part No: 110018030052-R; Package: 0402; Part_type: RESISTORS\FIXED; Project: AEGIS POM; RoHS: RoHS; Temperature: -55°C+155°C; Tolerance: NA; Voltage: NA; Wattage: 1/10W; Weight: 0.8mg; Datasheet: Y:\MIS_DATABASE\DATASHEETS\RESISTORS\PAN-ERJSER_NOV17.PDF
R70 = RESISTOR: RES 40.2K 1/16W 1% 0402; Chkd/date: VASANTHA/291216; Crtd /date: MAZHAR/170505; Custom_Duty: 15%; Customs_HS_Code: 85332119; Distributor_name: DIGIKEY; Distributor_part_number: 311-40.2KLRDKR-ND; Footprint Path: Y:\MIS_DATABASE\Library\ALTIUM_TOOL\PCB_FOOTPRINTS\Altium_Footprint_Lib.PcbLib; Height: 0.40MM; Library Path: Y:\MIS_DATABASE\Library\ALTIUM_TOOL\SCHEMATICS_PARTS\MS_DISCRETE_Library.schlib; Mfr_name: YAGEO AMERICA; Mfr_part_number: RC0402FR-0740K2L; Mistral Part No: 110009030811-R; Package: 0402; Part_type: RESISTORS\FIXED; Project: G4SLIM; RoHS: RoHS; Temperature: -55°C+155°C; Tolerance: 1%; Voltage: NA; Wattage: 1/16W; Weight: 0.65mg; Datasheet: Y:\MIS_DATABASE\DATASHEETS\RESISTORS\RCXXXXL-SER_MAR18.PDF
R342 = RESISTOR: RES 4.7K 1/16W 5% 0402; Assembly_Instruction: DNI; Chkd/date: VASANTHA/281216; Crtd /date: BAVISH/010611; Custom_Duty: 15%; Customs_HS_Code: 85332119; Distributor_name: DIGIKEY; Distributor_part_number: 541-4.7KJCT-ND; Footprint Path: Y:\MIS_DATABASE\Library\ALTIUM_TOOL\PCB_FOOTPRINTS\Altium_Footprint_Lib.PcbLib; Height: 0.40MM; Library Path: Y:\MIS_DATABASE\Library\ALTIUM_TOOL\SCHEMATICS_PARTS\MS_DISCRETE_Library.schlib; Mfr_name: VISHAY; Mfr_part_number: CRCW04024K70JNED; Mistral Part No: 110011060001-R; Package: 0402; Part_type: RESISTORS\FIXED; Project: AM4515_EVM_LCD; RoHS: RoHS; Temperature: -55°C+155°C; Tolerance: 5%; Voltage: NA; Wattage: 1/16W; Weight: 0.65mg; Datasheet: Y:\MIS_DATABASE\DATASHEETS\RESISTORS\CRCW0603.PDF
R353 = RESISTOR: RES 1.87K 1/10W 1% 0402; Chkd/date: MAZHAR/151208; Crtd /date: USMAN/251108; Custom_Duty: 15%; Customs_HS_Code: 85332119; Distributor_name: DIGIKEY; Distributor_part_number: P1.87KLCT-ND; Footprint Path: Y:\MIS_DATABASE\Library\ALTIUM_TOOL\PCB_FOOTPRINTS\Altium_Footprint_Lib.PcbLib; Height: 0.40MM; Library Path: Y:\MIS_DATABASE\Library\ALTIUM_TOOL\SCHEMATICS_PARTS\MS_DISCRETE_Library.schlib; Mfr_name: PANASONIC-ECG; Mfr_part_number: ERJ-2RKF1871X; Mistral Part No: 110009030145-R; Package: 0402; Part_type: RESISTORS\FIXED; Project: KHAN_HSST; RoHS: RoHS; Temperature: -55°C+155°C; Tolerance: 1%; Voltage: NA; Wattage: 1/10W; Weight: 0.8mg; Datasheet: Y:\MIS_DATABASE\DATASHEETS\RESISTORS\PAN-ERJSER_NOV17.PDF
TP15-TP18 TP24 TP26 TP31 = TESTPOINT: TESTPOINT CIR 40 SMD; Chkd/date: MAZHAR/190505; Crtd /date: MAZHAR/190505; Distributor_name: NA; Distributor_part_number: NA; Footprint Path: Y:\MIS_DATABASE\Library\ALTIUM_TOOL\PCB_FOOTPRINTS\Altium_Footprint_Lib.PcbLib; Height: NA; Library Path: Y:\MIS_DATABASE\Library\ALTIUM_TOOL\SCHEMATICS_PARTS\MS_DISCRETE_Library.schlib; MECHANICAL 3D STEP FILE: NA; Mfr_name: LOCAL; Mistral Part No: 130009030933; Package: SMD; Project: RAINIER-3; RoHS: NA; Temperature: NA; Tolerance: NA; Voltage: NA; Wattage: NA; Weight: NA; Datasheet: NA
TP136 = TESTPOINT: TESTPOINT CIR 20 SMD; Chkd/date: SHREESHAIL/171006; Crtd /date: MAZHAR/171006; Custom_Duty: NA; Customs_HS_Code: NA; Distributor_name: NA; Distributor_part_number: NA; Footprint Path: Y:\MIS_DATABASE\Library\ALTIUM_TOOL\PCB_FOOTPRINTS\Altium_Footprint_Lib.PcbLib; Height: NA; Library Path: Y:\MIS_DATABASE\Library\ALTIUM_TOOL\SCHEMATICS_PARTS\MS_DISCRETE_Library.schlib; MECHANICAL 3D STEP FILE: NA; Mfr_name: LOCAL; Mistral Part No: NA; Package: SMD; Project: BT MODULE_CSRBC04; RoHS: NA; Temperature: NA; Tolerance: NA; Voltage: NA; Wattage: NA; Weight: NA; Datasheet: NA
U8 = DS90UB921TRHSTQ1_WQFN48_TI: IC 5-96MHz 24BIT COLOR FPD-LINK III SERIALIZER WITH BI-DIR CONTROL CH WQFN48; Chkd/date: MANIRAJA/140618; Crtd /date: ALVY/140618; Custom_Duty: 15%; Customs_HS_Code: 85423100; Distributor_name: DIGIKEY; Distributor_part_number: 296-45288-1-ND; Footprint Path: Y:\MIS_DATABASE\Library\ALTIUM_TOOL\PCB_FOOTPRINTS\Altium_Footprint_Lib.PcbLib; Height: 0.80MM; Library Path: Y:\MIS_DATABASE\Library\ALTIUM_TOOL\SCHEMATICS_PARTS\MS_MISCINTERFACE_Library.schlib; Library Ref: DS90UB921TRHSTQ1_WQFN48; Mfr_name: TEXAS INSTRUMENTS; Mistral Part No: 141018060009-R; Package: WQFN48; Part_type: ICS\INTERFACE; Project: TI_J7SVB_FMZ-BOARD; RoHS: RoHS; Temperature: -40°C+105°C; Tolerance: NA; Voltage: NA; Wattage: NA; Weight: 40mg; Datasheet: Y:\MIS_DATABASE\DATASHEETS\ICS\INTERFACE\DS90UB921-Q1.PDF
U9 = PCA9306DCT_SSOP8: IC VOLTAGE LEVEL TRANSLATORS SSOP8; Chkd/date: MAZHAR/231210; Crtd /date: BAVISH/221210; Custom_Duty: 15%; Customs_HS_Code: 85423100; Distributor_name: DIGIKEY; Distributor_part_number: 296-18509-1-ND; Height: 1.30MM; Mfr_name: TEXAS INSTRUMENTS; Mfr_part_number: PCA9306DCTR; Mistral Part No: 141010120015-R; Package: SSOP8; Part_type: ICS\INTERFACE; Project: CENTAURUS; RoHS: RoHS; Temperature: -40°C+85°C; Tolerance: NA; Voltage: NA; Wattage: NA; Weight: NA; Datasheet: Y:\MIS_DATABASE\DATASHEETS\ICS\INTERFACE\PCA9306DCT.PDF
U42 = CDCE813QPWRQ1_TSSOP14: IC 1-PLL CLK SYNTHESIZER AND JITTER CLEANER WITH 2.5V AND 3.3V O/P TSSOP14; Chkd/date: MANIRAJA/160818; Crtd /date: MANIRAJA/160818; Custom_Duty: 15%; Customs_HS_Code: 85423100; Distributor_name: DIGIKEY; Distributor_part_number: 296-45498-1-ND; Footprint Path: Y:\MIS_DATABASE\Library\ALTIUM_TOOL\PCB_FOOTPRINTS\Altium_Footprint_Lib.PcbLib; Height: 1.20MM; Library Path: Y:\MIS_DATABASE\Library\ALTIUM_TOOL\SCHEMATICS_PARTS\MS_COMBINATIONAL_Library.schlib; Mfr_name: TEXAS INSTRUMENTS; Mfr_part_number: CDCE813QPWRQ1; Mistral Part No: 141018080006-R; Package: TSSOP14; Part_type: ICS\DIGITAL\COMBINATIONAL; Project: TI_J7ES_EVM_IB; RoHS: RoHS; Temperature: -40°C+105°C; Tolerance: NA; Voltage: NA; Wattage: NA; Weight: 173mg; Datasheet: Y:\MIS_DATABASE\DATASHEETS\ICS\DIGITAL\COMBINATIONAL\CDCE813QPWRQ1.PDF
U44 = TPS1H100A-Q1_HTSSOP14: IC 40V 100mE 1-CHANNEL SMART HIGH-SIDE POWER SWITCH HTSSOP14; Chkd/date: MANIRAJA/140818; Crtd /date: ALVY/140818; Custom_Duty: 15%; Customs_HS_Code: 85423100; Distributor_name: DIGIKEY; Distributor_part_number: 296-42052-1-ND; Footprint Path: Y:\MIS_DATABASE\Library\ALTIUM_TOOL\PCB_FOOTPRINTS\Altium_Footprint_Lib.PcbLib; Height: 1.20MM; Library Path: Y:\MIS_DATABASE\Library\ALTIUM_TOOL\SCHEMATICS_PARTS\MS_MISCPOWER_Library.schlib; Mfr_name: TEXAS INSTRUMENTS; Mistral Part No: 142018080008-R; Package: HTSSOP14; Part_type: ICS\POWER; Project: TI_J7ES_EVM_FUSION2_SER_CAP; RoHS: RoHS; Temperature: -40°C+125°C; Tolerance: NA; Voltage: NA; Wattage: NA; Weight: 58mg; Datasheet: Y:\MIS_DATABASE\DATASHEETS\ICS\POWER\TPS1H100-Q1.PDF
C1 C215 = CAP: CAP CERAMIC 2.2uF 16V 10% X7R 0805; Chkd/date: VASANTHA/061014; Crtd /date: MUDDU/250510; Custom_Duty: 15%; Customs_HS_Code: 85322990; Distributor_name: DIGIKEY; Distributor_part_number: 399-3523-1-ND; Footprint Path: Y:\MIS_DATABASE\Library\ALTIUM_TOOL\PCB_FOOTPRINTS\Altium_Footprint_Lib.PcbLib; Height: 1.40MM; Library Path: Y:\MIS_DATABASE\Library\ALTIUM_TOOL\SCHEMATICS_PARTS\MS_DISCRETE_Library.schlib; Mfr_name: KEMET; Mfr_part_number: C0805C225K4RACTU; Mistral Part No: 120010050002-R; Package: 0805; Part_type: CAPACITORS\CERAMIC; Project: NPOL_ADC; RoHS: RoHS; Temperature: -55°C+125°C; Tolerance: 10%; Voltage: 16V; Wattage: NA; Weight: 5.5mg; Datasheet: Y:\MIS_DATABASE\DATASHEETS\CAPACITORS\KEMET-C-X7R.PDF
C2 = CAP: CAP CERAMIC 1uF 16V 10% X5R 0402; Chkd/date: MANIRAJA/260618; Crtd /date: ALVY/260618; Custom_Duty: 15%; Customs_HS_Code: 85322990; Distributor_name: DIGIKEY; Distributor_part_number: 445-13181-1-ND; Footprint Path: Y:\MIS_DATABASE\Library\ALTIUM_TOOL\PCB_FOOTPRINTS\Altium_Footprint_Lib.PcbLib; Height: 0.33MM; Library Path: Y:\MIS_DATABASE\Library\ALTIUM_TOOL\SCHEMATICS_PARTS\MS_DISCRETE_Library.schlib; Mfr_name: TDK CORPORATION; Mfr_part_number: CGB2A1X5R1C105K033BC; Mistral Part No: 120018060036-R; Package: 0402; Part_type: CAPACITORS\CERAMIC; Project: MYTHIC_PCIE_DB; RoHS: RoHS; Temperature: -55°C+85°C; Tolerance: 10%; Voltage: 16V; Wattage: NA; Weight: 0.65mg; Datasheet: Y:\MIS_DATABASE\DATASHEETS\CAPACITORS\TDK-CG-SER.PDF
J3 = RECP_16X2: CON RECP 2X16 2.54MM PITCH RT TH; Chkd/date: MANIRAJA/180917; Crtd /date: MANIRAJA/180917; Custom_Duty: 24%; Customs_HS_Code: 85369090; Distributor_name: DIGIKEY; Distributor_part_number: SSQ-116-02-L-D-RA-ND; Height: 4.95MM; Mfr_name: SAMTEC; Mfr_part_number: SSQ-116-02-L-D-RA; Mistral Part No: 150017090017-R; Package: THRU-HOLE; Part_type: CONNECTOR\RECEPTACLE; Project: TI_SVB_MAXWELL_FMB; RoHS: RoHS; Temperature: -55°C+125°C; Tolerance: NA; Voltage: NA; Wattage: NA; Weight: NA; Datasheet: Y:\MIS_DATABASE\DATASHEETS\CONNECTORS\SSQ_TH.PDF
J6 = CON_FLEX_36X1_52559-3652: CON FPC 1X36 0.50MM PITCH ST SMD; Chkd/date: MANIRAJA/060917; Crtd /date: MANIRAJA/060917; Custom_Duty: 24%; Customs_HS_Code: 85369090; Distributor_name: DIGIKEY; Distributor_part_number: WM7988CT-ND; Height: 5.30MM; Mfr_name: MOLEX; Mfr_part_number: 52559-3652; Mistral Part No: 150017090006-R; Package: SMD; Part_type: CONNECTOR\FPC; Project: TI_SVB_MAXWELL_DUT; RoHS: RoHS; Temperature: -40°C+85°C; Tolerance: NA; Voltage: NA; Wattage: NA; Weight: 429.23mg; Datasheet: Y:\MIS_DATABASE\DATASHEETS\CONNECTORS\52559.PDF
U1 = TLV7103318D_WSON6: IC REGULATOR LDO LINEAR 200mA WSON6; Chkd/date: NAVEED/080415; Crtd /date: JEBRAN/300315; Custom_Duty: 15%; Customs_HS_Code: 85423100; Distributor_name: DIGIKEY; Distributor_part_number: 296-29058-1-ND; Height: 0.80MM; Mfr_name: TEXAS INSTRUMENTS; Mistral Part No: 142015030017-R; Package: WSON6; Part_type: ICS\POWER\VOLTAGE REGULATOR; Project: DUET BOARDS; RoHS: RoHS; Temperature: -40°C+125°C; Tolerance: NA; Voltage: NA; Wattage: NA; Weight: NA; Datasheet: Y:\MIS_DATABASE\DATASHEETS\MISC\REGULATORS\TLV71-SER.PDF
U35 = SN74LVC2G125DCUT_VSSOP8: IC DUAL BUS BUFFER GATE VSSOP8; Chkd/date: SHREESHAIL/060607; Crtd /date: MAZHAR/170107; Custom_Duty: 15%; Customs_HS_Code: 85423100; Distributor_name: DIGIKEY; Distributor_part_number: 296-13265-1-ND; Height: 0.90MM; Mfr_name: TEXAS INSTRUMENTS; Mistral Part No: 141009030242-R; Package: VSSOP8; Part_type: ICS\DIGITAL\GATES; Project: OMAP2430_OSK; RoHS: RoHS; Temperature: -40°C+85°C; Tolerance: NA; Voltage: NA; Wattage: NA; Weight: NA; Datasheet: Y:\MIS_DATABASE\DATASHEETS\ICS\DIGITAL\GATES\SN74LVC2G125.PDF
U38 = OSC4_ASDMB: OSC 24.000MHz SMD; Chkd/date: VASANTHA/280616; Crtd /date: VASANTHA/280616; Custom_Duty: 15%; Customs_HS_Code: 85412900; Distributor_name: DIGIKEY; Distributor_part_number: 535-11728-1-ND; Height: 0.90MM; Mfr_name: ABRACON CORPORATION; Mfr_part_number: ASDMB-24.000MHZ-LC-T; Mistral Part No: 130016060075-R; Package: SMD; Part_type: OSCILLATORS; Project: RZ/G1E _SOM; RoHS: RoHS; Temperature: -40°C+85°C; Tolerance: NA; Voltage: NA; Wattage: NA; Weight: NA; Datasheet: Y:\MIS_DATABASE\DATASHEETS\MISC\CRY_OSC\ASDMB.PDF

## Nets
DGND: C1.2 C2.2 C3.2 C4.2 C5.2 C7.2 C10.2 C19.2 C22.2 C28.2 C29.2 C32.2 C35.2 C38.2 C39.2 C40.2 C41.2 C42.1 C43.2 C44.2 C210.2 C211.2 C212.2 C214.2 C215.2 C216.2 C218.2 C221.2 C224.2 C252.2 C253.2 C254.2 C255.2 C257.2 C258.2 C259.1 C260.2 C264.2 D4.2(ANODE) J3.16 J3.18 J3.22 J3.31 J3.32 J6.6 J6.8 J6.10 J6.25 J6.26 J6.SH1 J6.SH2 J6.SH3 J6.SH4 J7.4 J7.SH1 J7.SH2 J7.SH3 J7.SH4 R1.1 R10.1 R23.2 R24.2 R47.1 R55.1 R70.2 R71.2 R311.2 R314.2 R321.2 R336.2 R342.2 R349.2 R353.2 U1.4(GND) U8.49(GND) U9.1(GND) U35.4(GND) U38.2(GND) U42.5(GND) U42.10(GND) U44.2(GND) U44.15(EP) ; also on sheet 5 6 7 8 9 10 11 12 13 14 15 18 19 20 21 22 23 25
VCC_1V8: C258.1 FL23.1 R54.1 R68.1 R69.1 R339.1 U9.2(VREF1) ; also on sheet 5
VCC_3V3: C39.1 C40.1 C43.1 C44.1 C224.1 FL6.2 FL15.1 FL24.2 R20.1 R30.2 R56.1 R62.1 R64.1 U8.30(VDDIO) ; also on sheet 5 14 15 18 19 20 21 22 23 25
VCC_5V0: C4.1 FL1.1 ; also on sheet 5 6 9 14 15 22 23
VCC_12V: C260.1 C264.1 U44.8(VS) U44.9(VS) U44.10(VS) ; also on sheet 5 18 20
VCC_12V_CON: C257.1 C259.2 D4.1(CATHODE) J7.2 U44.5(OUT1) U44.6(OUT2) U44.7(OUT3)
VCC_CAM_3V3: C19.1 C22.1 C218.1 C221.1 FL15.2 J6.1 J6.2 J6.3
VCC_CAM_5V0: C2.1 C3.1 C5.1 C7.1 C10.1 C210.1 C211.1 C212.1 FL1.2 J3.19 J3.21 J6.4 J6.5 U1.2(IN) U1.3(EN2)
VCC_CAM_IO: C1.1 C214.1 FL14.1 R1.2 R2.2 R3.2 R11.2 R313.1 U35.8(VCC) ; also on sheet 21
VCC_CAM_OSC: C215.1 C216.1 FL14.2 R326.1 U38.4(VDD)
VDD33_FPD: C41.1 FL6.1 U8.22(VDD33)
VDD_CDCE: C253.1 C255.1 FL23.2 U42.3(VDD)
VDDOUT_CDCE: C252.1 C254.1 FL24.1 U42.6(VDDOUT) U42.7(VDDOUT)
C_FPD_DOUT_N: C36.1 U8.19(DOUT-)
C_FPD_DOUT_P: C37.1 U8.20(DOUT+)
CAM_EXT_CLK: U35.2(1A) U35.5(2A) U38.3(OUTPUT)
CAM_I2C_SCL: J3.14 J6.29 ; also on sheet 21
CAM_I2C_SDA: J3.12 J6.30 ; also on sheet 21
CAM_LI_EXT_CLK: J6.7 R323.2
CAM_OV_EXT_CLK: J3.20 R315.2
CAM_VIO_SEL: U1.1(EN1) ; also on sheet 5
CDCE_1V8_I2C_SCL: R68.2 U9.3(SCL1) U42.12(SCL/S2)
CDCE_1V8_I2C_SDA: R69.2 U9.4(SDA1) U42.13(SDA/S1)
CDCE_PCLK: R22.2 R23.1 TP136.1(TP) U42.1(XIN/CLK)
CDCE_S0: R339.2 R342.1 U42.2(S0)
CDCE_VCTR: R54.2 U42.4(VCTR)
CDCE_Y1: R27.1 R63.1
CMC_FPD_DOUT_N: C36.2 FL5.2
CMC_FPD_DOUT_P: C37.2 FL5.1
CON_UB921_INTB: R65.2 ; also on sheet 5
FPD_DE: U8.5(DE) ; also on sheet 14
FPD_DOUT_N: FL5.3 J7.3
FPD_DOUT_P: FL5.4 J7.1
FPD_HSYNC: U8.3(HS) ; also on sheet 14
FPD_PCLK: R22.1 R26.1 ; also on sheet 14
FPD_VSYNC: U8.4(VS) ; also on sheet 14
I2C1_SCL: R50.2 U8.8(SCL) ; also on sheet 5 15
I2C1_SDA: R51.2 U8.9(SDA) ; also on sheet 5 15
LI_CAM_RST#: J6.33 R11.1 ; also on sheet 21
LI_CAM_TRIGGER: J6.35 R10.2 ; also on sheet 21
LI_SPI3_CLK: J6.32 ; also on sheet 21
LI_SPI3_CS0: J6.34 ; also on sheet 21
LI_SPI3_MISO: J6.31 ; also on sheet 21
LI_SPI3_MOSI: J6.36 ; also on sheet 21
LI_VIN_DATA0: J6.28 ; also on sheet 21
LI_VIN_DATA1: J6.27 ; also on sheet 21
LI_VIN_DATA2: J6.24 ; also on sheet 21
LI_VIN_DATA3: J6.23 ; also on sheet 21
LI_VIN_DATA4: J6.22 ; also on sheet 21
LI_VIN_DATA5: J6.21 ; also on sheet 21
LI_VIN_DATA6: J6.20 ; also on sheet 21
LI_VIN_DATA7: J6.19 ; also on sheet 21
LI_VIN_DATA8: J6.18 ; also on sheet 21
LI_VIN_DATA9: J6.17 ; also on sheet 21
LI_VIN_DATA10: J6.16 ; also on sheet 21
LI_VIN_DATA11: J6.15 ; also on sheet 21
LI_VIN_DATA12: J6.14 ; also on sheet 21
LI_VIN_DATA13: J6.13 ; also on sheet 21
LI_VIN_HD: J6.12 TP18.1(TP) ; also on sheet 21
LI_VIN_PCLK: R324.1 TP26.1(TP) ; also on sheet 21
LI_VIN_VD: J6.11 TP24.1(TP) ; also on sheet 21
OV_CAM_PWDN: R318.2 ; also on sheet 21
OV_VIN_DATA0: J3.26 ; also on sheet 21
OV_VIN_DATA1: J3.25 ; also on sheet 21
OV_VIN_DATA2: J3.24 ; also on sheet 21
OV_VIN_DATA3: J3.23 ; also on sheet 21
OV_VIN_DATA4: J3.2 ; also on sheet 21
OV_VIN_DATA5: J3.1 ; also on sheet 21
OV_VIN_DATA6: J3.4 ; also on sheet 21
OV_VIN_DATA7: J3.3 ; also on sheet 21
OV_VIN_DATA8: J3.6 ; also on sheet 21
OV_VIN_DATA9: J3.5 ; also on sheet 21
OV_VIN_DATA10: J3.8 ; also on sheet 21
OV_VIN_DATA11: J3.7 ; also on sheet 21
OV_VIN_HD: J3.13 TP16.1(TP) ; also on sheet 21
OV_VIN_PCLK: R312.1 TP17.1(TP) ; also on sheet 21
OV_VIN_PCLK_R: J3.17 R312.2
OV_VIN_VD: J3.15 TP15.1(TP) ; also on sheet 21
PCLK_R: R26.2 R27.2 U8.10(PCLK)
PWR_SW_UB921: R71.1 U44.3(IN) ; also on sheet 5
R_CDCE_Y1: R63.2 U42.11(Y1)
R_LI_VIN_PCLK: J6.9 R324.2
R_OV_CAM_PWDN: J3.10 R311.1 R313.2 R318.1
U66_CL: R353.1 U44.13(CL)
U66_DIAG_EN: R349.1 U44.12(DIAG_EN)
UB921_DIN0: U8.43(GPO_REG4/B0/DIN16) ; also on sheet 14
UB921_DIN1: U8.44(GPO_REG5/B1/DIN17) ; also on sheet 14
UB921_DIN2: U8.45(B2/DIN18) ; also on sheet 14
UB921_DIN3: U8.46(B3/DIN19) ; also on sheet 14
UB921_DIN4: U8.47(B4/DIN20) ; also on sheet 14
UB921_DIN5: U8.48(B5/DIN21) ; also on sheet 14
UB921_DIN6: U8.1(B6/DIN22) ; also on sheet 14
UB921_DIN7: U8.2(B7/DIN23) ; also on sheet 14
UB921_DIN8: U8.35(DIN8/G0/GPIO2) ; also on sheet 14
UB921_DIN9: U8.36(DIN9/G1/GPIO3) ; also on sheet 14
UB921_DIN10: U8.37(G2/DIN10) ; also on sheet 14
UB921_DIN11: U8.38(G3_/_DIN11) ; also on sheet 14
UB921_DIN12: U8.39(G4/DIN12) ; also on sheet 14
UB921_DIN13: U8.40(G5/DIN13) ; also on sheet 14
UB921_DIN14: U8.41(G6/DIN14) ; also on sheet 14
UB921_DIN15: U8.42(G7/DIN15) ; also on sheet 14
UB921_DIN16: U8.25(DIN0/R0/GPIO0) ; also on sheet 14
UB921_DIN17: U8.26(DIN1/R1/GPIO1) ; also on sheet 14
UB921_DIN18: U8.27(DIN2/R2) ; also on sheet 14
UB921_DIN19: U8.28(DIN3/R3) ; also on sheet 14
UB921_DIN20: U8.29(DIN4/R4) ; also on sheet 14
UB921_DIN21: U8.32(DIN5/R5) ; also on sheet 14
UB921_DIN22: U8.33(DIN6/R6) ; also on sheet 14
UB921_DIN23: U8.34(DIN7/R7) ; also on sheet 14
UB921_FSEL: R30.1 R336.1 U8.15(FSEL)
UB921_IDX: R20.2 R24.1 U8.6(IDX)
UB921_INTB: R66.2 ; also on sheet 5
UB921_INTB_R: R64.2 R65.1 R66.1 U8.31(INTB)
UB921_MODE_SEL: R62.2 R70.1 U8.24(MODE_SEL)
UB921_REM_INTB: TP31.1(TP) U8.16(REM_INTB)
UB921_RESETn: R55.2 U8.21(PDB) ; also on sheet 5
VLDO_CAM_1V8: R2.1 U1.5(OUT2)
VLDO_CAM_3V3: R3.1 U1.6(OUT1)
N19811491: C42.2 U8.23(CMF)
N19811520: R47.2 U8.18(RES1)
N19811540: C32.1 U8.14(CAPP12)
N19811568: C35.1 U8.17(CAPHS12)
N19811570: C28.1 C29.1 U8.7(CAPL12)
N24561941: R50.1 U9.6(SCL2)
N24561944: R51.1 U9.5(SDA2)
N24562809: C38.1 R56.2 U9.7(VREF2) U9.8(EN)
N24636980: R315.1 U35.6(1Y)
N24637007: R323.1 U35.3(2Y)
N24638437: R326.2 U38.1(STANDBY)
N24733661: R314.1 U35.7(\\~{2}\\~{O}\\E)
N24733666: R321.1 U35.1(\\~{1}\\~{O}\E)

Not connected (* = marked no-connect by the designer): J3 9* 11* 27* 28* 29* 30*; U8 11(GPO_REG6/I2S_DA) 12(GPO_REG7/I2S_WC) 13(I2S_CLK); U42 8(Y3)* 9(Y2)* 14(XOUT)*; U44 1(NC1)* 4(NC2)* 11(NC3)* 14(~{ST})*

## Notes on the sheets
sheet 16
- FPD LINK-III DISPLAY SERIALIZER
- FPD-Link III Interface
- PCB Note:  Place Capacitor close to IC pin
- 100E
- [UB921_PDB]
- PCB Note:  Place near to HSD Connector
- From Mux
  (HDMI/FPD-Link/Cam)
- Silkscreen:
  "FPD-Link Display"
- Connector / Transmitter
- Pin 1: DOUT+
- Pin 2: PWR
- Pin 3: DOUT-
- Pin 4: GND
- Display Panel Power
- Load Switch
- PCB Note:  Connect to GND plane with at least 9 vias.
- PCB Note: Place together to
  minimize stub.
- Serializer Settings
- See "R1" in table
- See "R2" in table
- 7b' I2C Address
- R20
- R24
- 0x1A (default)
- 30.9K
- 95.3K
- (other - see DM)
- Note: I2C ADDR 0x65
- Alternate Clock/Cleaner (Option)
sheet 17
- CAMERA MODULE INTERFACES
- Camera IO Voltage Selection
- Note: Resistor is to 'bleed' off voltage.
- OmniVision Camera Moduel Interface
- Leopard Imaging Camera Module Interface
- [VCC_3V3]
- [VCC_5V0]
- [I2C_SDA]
- [I2C_SCL]
- [EXT_REFCLK]
- Silkscreen:
  "CAMERA-OMNI"
- PCB Note: Place visibility test points to minimize stubs.
- [I2C_SCL]
- [I2C_SDA]
- Camera Reference Clock (Optional)
- Silkscreen:
  "CAMERA-LI"
- PCB Note: Place visibility test points to minimize stubs.
